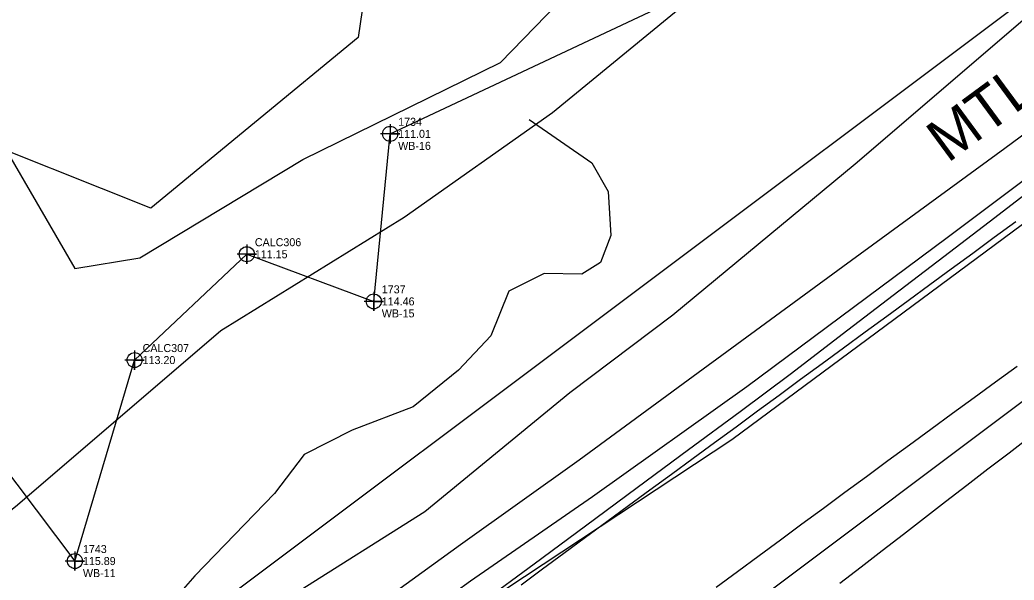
# Model space of a CAD drawing. Extents: x 2186615 to 2188822, y 629899 to 631820.
# Drawn here: x 2187253.2 to 2187346.4, y 630519.4 to 630571.8 of the extents above; entities that cross this region are included whole.
import ezdxf

# ---------------------------------------------------------------- set-up
doc = ezdxf.new("R2010")
doc.units = 0
for name, color, linetype in [('Exist Environmental Wetland Boundary', 7, 'Continuous'), ('Exist Environmental Wetland Boundary Cogo Comment', 7, 'Continuous'), ('Exist Environmental Wetland Boundary Cogo Elevation', 7, 'Continuous'), ('Exist Environmental Wetland Boundary Cogo Number', 7, 'Continuous'), ('Exist Environmental Wetland Boundary Cogo Point CELL', 7, 'Continuous'), ('Exist Guardrail', 7, 'Continuous'), ('Exist Guardrail Text', 7, 'Continuous'), ('Exist Horizontal Alignment', 7, 'Continuous'), ('Exist Hydro Stream or Body of Water', 7, 'Continuous'), ('Exist Right of Way Line', 7, 'Continuous'), ('Exist Roads EOP', 7, 'Continuous'), ('Exist Roads EOT', 7, 'Continuous'), ('Exist Utilities Gas UG Line SUE LOS B', 7, 'Continuous'), ('Exist Utilities Telephone UG FO SUE LOS B', 7, 'Continuous'), ('Exist Utilities Water UG Line SUE LOS B', 7, 'Continuous'), ('Exist Vegetation Hedge Row', 7, 'Continuous'), ('Exist Vegetation Woods Line', 7, 'Continuous')]:
    doc.layers.add(name, color=color, linetype=linetype)

msp = doc.modelspace()

# ---------------------------------------------------------------- linework, layer by layer
at = {"layer": 'Exist Environmental Wetland Boundary'}
msp.add_lwpolyline([(2187196.863, 630579.007), (2187215.669, 630565.573), (2187228.296, 630540.413), (2187243.76, 630540.495), (2187258.391, 630521.139), (2187263.982, 630539.962), (2187274.494, 630549.875), (2187286.387, 630545.46), (2187287.922, 630561.151), (2187317.905, 630575.266)], dxfattribs=at)
at = {"layer": 'Exist Environmental Wetland Boundary Cogo Point CELL'}
for points in [[(2187287.922, 630562.051), (2187287.922, 630560.251), (2187287.922, 630561.151), (2187288.822, 630561.151), (2187287.022, 630561.151)], [(2187274.494, 630550.775), (2187274.494, 630548.975), (2187274.494, 630549.875), (2187275.394, 630549.875), (2187273.594, 630549.875)], [(2187286.387, 630546.36), (2187286.387, 630544.56), (2187286.387, 630545.46), (2187287.287, 630545.46), (2187285.487, 630545.46)], [(2187263.982, 630540.862), (2187263.982, 630539.062), (2187263.982, 630539.962), (2187264.882, 630539.962), (2187263.082, 630539.962)], [(2187258.391, 630522.039), (2187258.391, 630520.239), (2187258.391, 630521.139), (2187259.291, 630521.139), (2187257.491, 630521.139)]]:
    msp.add_lwpolyline(points, dxfattribs=at)
for centre in [(2187287.922, 630561.151), (2187274.494, 630549.875), (2187286.387, 630545.46), (2187263.982, 630539.962), (2187258.391, 630521.139)]:
    msp.add_circle(centre, 0.703, dxfattribs=at)
at = {"layer": 'Exist Guardrail'}
msp.add_lwpolyline([(2187241.55, 630486.346), (2187253.35, 630494.155), (2187264.205, 630501.541), (2187275.163, 630508.92), (2187284.892, 630515.715), (2187294.523, 630522.691), (2187305.629, 630530.633), (2187316.311, 630538.47), (2187330.339, 630548.737), (2187345.501, 630559.821), (2187361.866, 630571.876), (2187380.98, 630586.026), (2187387.099, 630590.708), (2187395.301, 630597.179), (2187406.457, 630605.967), (2187415.255, 630612.832), (2187425.741, 630621.13)], dxfattribs=at)
at = {"layer": 'Exist Horizontal Alignment'}
msp.add_line((2187136.406, 630378.107), (2188520.855, 631416.042), dxfattribs=at)
at = {"layer": 'Exist Hydro Stream or Body of Water'}
msp.add_lwpolyline([(2187355.024, 630682.108), (2187359.111, 630660.656), (2187365.552, 630646.993), (2187357.69, 630636.565), (2187357.397, 630627.181), (2187350.161, 630611.43), (2187334.761, 630604.35), (2187327.139, 630603.043), (2187305.441, 630602.027), (2187285.871, 630601.097), (2187286.965, 630584.075), (2187284.925, 630570.17), (2187265.503, 630554.196), (2187246.837, 630561.617), (2187236.716, 630578.631), (2187228.746, 630591.985), (2187226.121, 630610.409)], dxfattribs=at)
at = {"layer": 'Exist Right of Way Line'}
msp.add_line((2187118.411, 630402.11), (2188502.827, 631440.021), dxfattribs=at)
msp.add_arc((2191071.837, 625294.065), 6398.299, 123.691884, 125.6572198, dxfattribs=at)
at = {"layer": 'Exist Roads EOP'}
msp.add_lwpolyline([(2187253.251, 630485.092), (2187258.089, 630488.64), (2187262.927, 630492.187), (2187267.738, 630495.773), (2187272.517, 630499.4), (2187277.296, 630503.028), (2187282.075, 630506.656), (2187286.886, 630510.241), (2187291.726, 630513.787), (2187296.566, 630517.333), (2187301.404, 630520.881), (2187306.229, 630524.448), (2187311.052, 630528.017), (2187315.874, 630531.586), (2187320.697, 630535.155), (2187325.509, 630538.739), (2187330.275, 630542.382), (2187335.039, 630546.03), (2187339.802, 630549.678), (2187344.565, 630553.327), (2187349.328, 630556.974)], dxfattribs=at)
at = {"layer": 'Exist Roads EOT'}
for points in [[(2187300.18, 630518.92), (2187302.192, 630520.404), (2187304.204, 630521.888), (2187306.217, 630523.37), (2187308.232, 630524.85), (2187310.247, 630526.329), (2187312.263, 630527.808), (2187314.278, 630529.287), (2187316.294, 630530.765), (2187318.309, 630532.244), (2187320.325, 630533.723), (2187322.341, 630535.202), (2187324.356, 630536.68), (2187326.372, 630538.159), (2187328.388, 630539.638), (2187330.403, 630541.117), (2187332.419, 630542.595), (2187334.434, 630544.074), (2187336.449, 630545.553), (2187338.465, 630547.032), (2187340.48, 630548.511), (2187342.496, 630549.99), (2187344.511, 630551.47), (2187346.527, 630552.949)], [(2187318.453, 630518.68), (2187320.465, 630520.164), (2187322.477, 630521.647), (2187324.49, 630523.131), (2187326.502, 630524.614), (2187328.514, 630526.098), (2187330.526, 630527.581), (2187332.539, 630529.064), (2187334.552, 630530.545), (2187336.569, 630532.023), (2187338.586, 630533.5), (2187340.603, 630534.976), (2187342.62, 630536.453), (2187344.638, 630537.93), (2187346.655, 630539.407)], [(2187330.061, 630519.072), (2187332.041, 630520.599), (2187334.02, 630522.126), (2187336, 630523.653), (2187337.979, 630525.18), (2187339.958, 630526.707), (2187341.938, 630528.234), (2187343.917, 630529.762), (2187345.895, 630531.29), (2187347.873, 630532.819)]]:
    msp.add_lwpolyline(points, dxfattribs=at)
at = {"layer": 'Exist Utilities Gas UG Line SUE LOS B'}
msp.add_lwpolyline([(2187126.474, 630392.391), (2187146.749, 630408.061), (2187165.948, 630422.166), (2187183.003, 630435.52), (2187198.842, 630447.531), (2187220.79, 630463.611), (2187230.742, 630480.093), (2187238.842, 630491.282), (2187252.932, 630500.782), (2187264.616, 630507.024), (2187278.901, 630518.022), (2187291.156, 630525.789), (2187304.759, 630536.934), (2187314.395, 630544.202), (2187331.496, 630558.331), (2187350.478, 630574.64)], dxfattribs=at)
at = {"layer": 'Exist Utilities Telephone UG FO SUE LOS B'}
msp.add_lwpolyline([(2187221.787, 630477.44), (2187244.494, 630488.549), (2187260.766, 630497.303), (2187273.174, 630505.002), (2187293.431, 630514.995), (2187319.925, 630532.538), (2187378.478, 630575.929), (2187483.974, 630656.576), (2187503.962, 630671.26), (2187608.063, 630745.856)], dxfattribs=at)
at = {"layer": 'Exist Utilities Water UG Line SUE LOS B'}
msp.add_lwpolyline([(2187188.37, 630443.024), (2187206.689, 630458.058), (2187226.474, 630471.999), (2187238.766, 630480.882), (2187255.867, 630491.296), (2187266.081, 630498.059), (2187295.46, 630519.284), (2187306.869, 630527.171), (2187321.342, 630537.501), (2187340.106, 630551.443), (2187356.85, 630563.988), (2187378.548, 630580.267)], dxfattribs=at)
at = {"layer": 'Exist Vegetation Hedge Row'}
msp.add_lwpolyline([(2187300.929, 630562.484), (2187306.827, 630558.442), (2187308.329, 630555.745), (2187308.601, 630551.641), (2187307.631, 630549.109), (2187305.892, 630548.006), (2187302.34, 630548.066), (2187299.032, 630546.426), (2187297.353, 630542.227), (2187294.333, 630539.009), (2187290.065, 630535.596), (2187284.36, 630533.382), (2187279.853, 630531.121), (2187277.082, 630527.469), (2187269.632, 630519.747), (2187264.825, 630514.256), (2187260.302, 630510.672), (2187252.455, 630505.696)], dxfattribs=at)
at = {"layer": 'Exist Vegetation Woods Line'}
for points in [[(2187353.136, 630599.668), (2187345.325, 630594.997), (2187335.37, 630594.014), (2187327.95, 630588.476), (2187319.257, 630576.371), (2187303.138, 630563.124), (2187289.247, 630553.308), (2187272.051, 630542.696)], [(2187241.527, 630578.901), (2187245.792, 630570.178), (2187258.391, 630548.54), (2187264.482, 630549.542), (2187279.743, 630558.733), (2187298.244, 630567.832), (2187312.219, 630582.214)], [(2187272.051, 630542.696), (2187253.013, 630526.361), (2187251.556, 630525.183), (2187245.608, 630523.938), (2187235.905, 630524.691), (2187226.684, 630526.939), (2187216.198, 630531.636), (2187205.555, 630544.345), (2187195.902, 630560.507), (2187189.52, 630569.738), (2187187.426, 630571.334)]]:
    msp.add_lwpolyline(points, dxfattribs=at)

# ---------------------------------------------------------------- texts
at = {"layer": 'Exist Environmental Wetland Boundary Cogo Comment'}
for s, p in [('WB-16', (2187288.672, 630559.651)), ('WB-15', (2187287.137, 630543.96)), ('WB-11', (2187259.141, 630519.639))]:
    msp.add_text(s, height=0.75, dxfattribs=at).set_placement(p)
at = {"layer": 'Exist Environmental Wetland Boundary Cogo Elevation'}
for s, p in [('111.01', (2187288.672, 630560.776)), ('111.15', (2187275.244, 630549.5)), ('114.46', (2187287.137, 630545.085)), ('113.20', (2187264.732, 630539.587)), ('115.89', (2187259.141, 630520.764))]:
    msp.add_text(s, height=0.75, dxfattribs=at).set_placement(p)
at = {"layer": 'Exist Environmental Wetland Boundary Cogo Number'}
for s, p in [('1734', (2187288.672, 630561.901)), ('CALC306', (2187275.244, 630550.625)), ('1737', (2187287.137, 630546.21)), ('CALC307', (2187264.732, 630540.712)), ('1743', (2187259.141, 630521.889))]:
    msp.add_text(s, height=0.75, dxfattribs=at).set_placement(p)
at = {"layer": 'Exist Guardrail Text'}
msp.add_text('MTL', height=4, rotation=36.37645, dxfattribs=at).set_placement((2187340.15, 630558.364))

doc.saveas('drawing.dxf')
